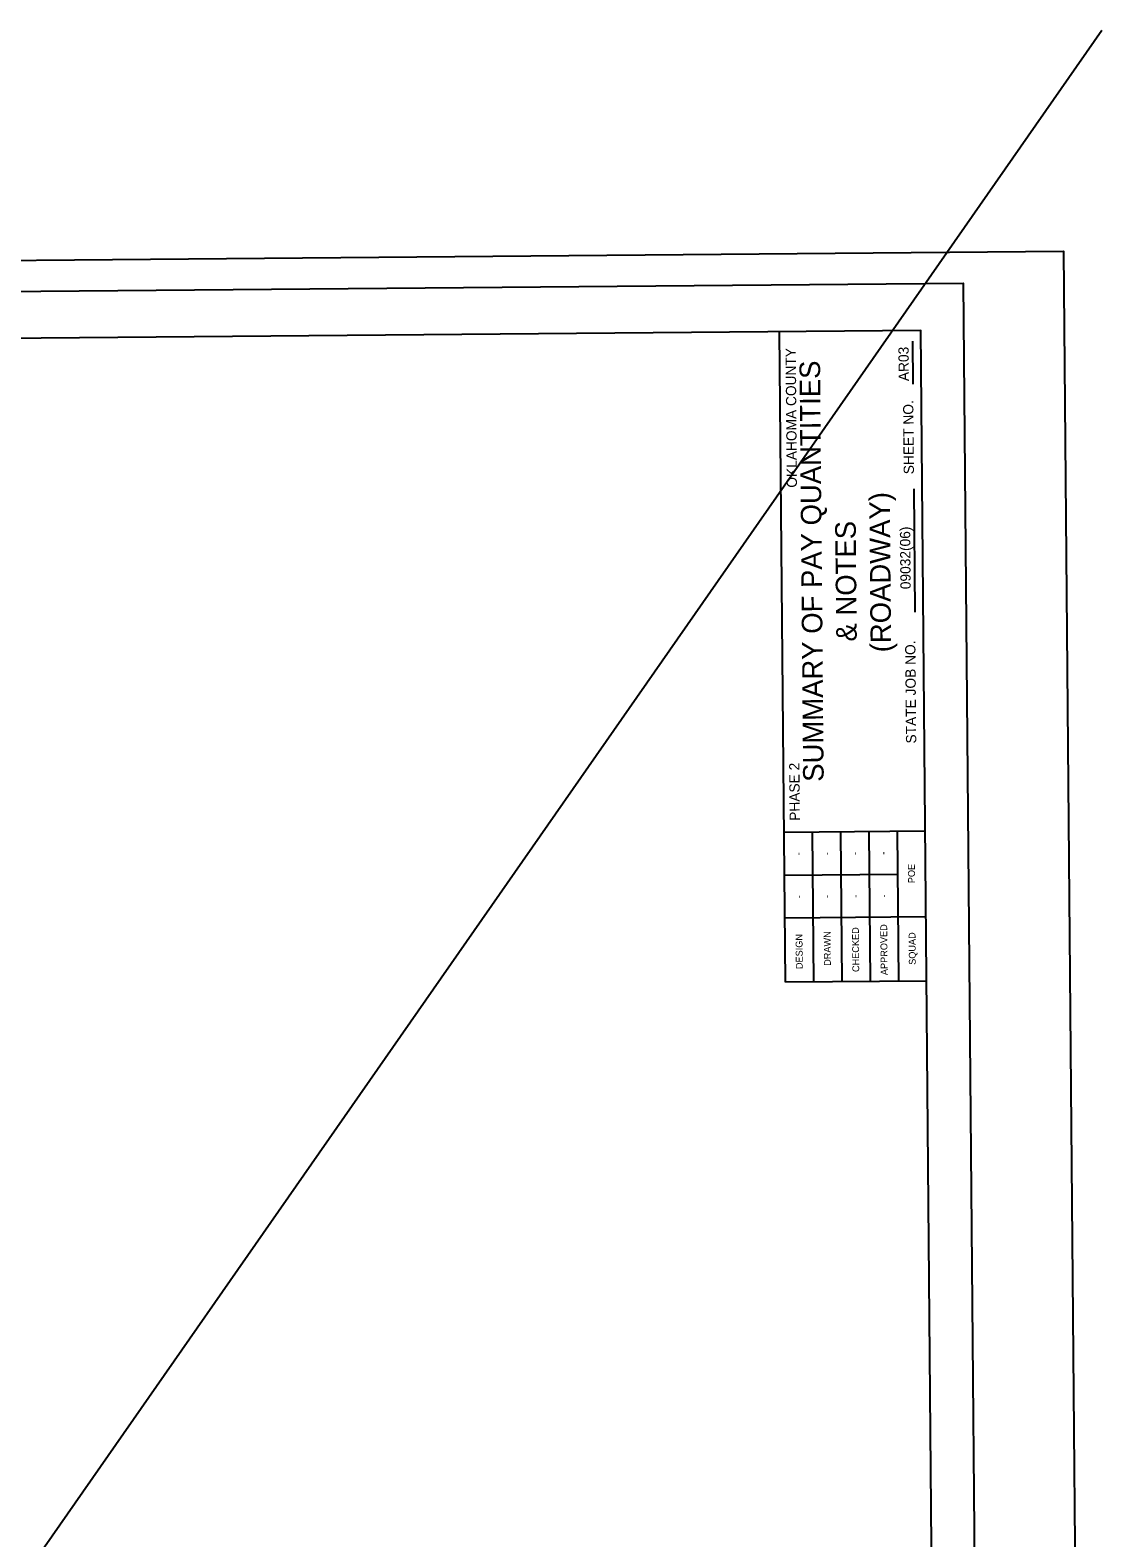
# Model space of a CAD drawing. Extents: x 2151899 to 2151927, y 142567 to 142686.
# Drawn here: x 2151912.01 to 2151924.52, y 142668.37 to 142685.99 of the extents above; entities that cross this region are included whole.
import ezdxf

# ---------------------------------------------------------------- set-up
doc = ezdxf.new("R2010")
doc.units = 0
for name, color, linetype in [('Default', 7, 'Continuous'), ('SHT_Plot_Shape_Full', 7, 'Continuous'), ('SHT_Plot_Shape_Half', 7, 'Continuous'), ('SHT_Sheet_Border', 7, 'Continuous'), ('SHT_Standard_Sheet_Lines', 7, 'Continuous'), ('SHT_Standard_Sheet_Txt', 7, 'Continuous')]:
    doc.layers.add(name, color=color, linetype=linetype)

msp = doc.modelspace()

# ---------------------------------------------------------------- linework, layer by layer
at = {"layer": 'Default'}
msp.add_line((2151899.488, 142650.069), (2151924.522, 142685.989), dxfattribs=at)
at = {"layer": 'SHT_Plot_Shape_Full'}
msp.add_lwpolyline([(2151900.392, 142647.197), (2151900.077, 142683.196), (2151924.076, 142683.406), (2151924.391, 142647.407)], close=True, dxfattribs=at)
at = {"layer": 'SHT_Plot_Shape_Half'}
msp.add_lwpolyline([(2151901.203, 142648.842), (2151900.905, 142682.841), (2151922.904, 142683.033), (2151923.202, 142649.034)], close=True, dxfattribs=at)
at = {"layer": 'SHT_Sheet_Border'}
for p, q in [((2151920.826, 142674.865), (2151920.759, 142682.464)), ((2151922.46, 142676.629), (2151920.809, 142676.614)), ((2151922.476, 142674.879), (2151920.826, 142674.865))]:
    msp.add_line(p, q, dxfattribs=at)
msp.add_lwpolyline([(2151922.685, 142650.98), (2151922.409, 142682.479), (2151901.41, 142682.295), (2151901.686, 142650.796)], close=True, dxfattribs=at)
at = {"layer": 'SHT_Standard_Sheet_Lines'}
for p, q in [((2151922.318, 142681.853), (2151922.314, 142682.356)), ((2151922.342, 142679.189), (2151922.329, 142680.629)), ((2151922.134, 142676.126), (2151920.814, 142676.114)), ((2151922.469, 142675.629), (2151920.818, 142675.614))]:
    msp.add_line(p, q, dxfattribs=at)
for points in [[(2151921.14, 142676.617), (2151921.156, 142674.867)], [(2151921.47, 142676.62), (2151921.486, 142674.87)], [(2151921.8, 142676.623), (2151921.816, 142674.873)], [(2151922.13, 142676.626), (2151922.146, 142674.876)]]:
    msp.add_lwpolyline(points, dxfattribs=at)

# ---------------------------------------------------------------- texts
at = {"layer": 'SHT_Standard_Sheet_Txt'}
for s, height, p in [('OKLAHOMA COUNTY', 0.12, (2151920.962, 142680.644)), ('AR03', 0.12, (2151922.269, 142681.889)), ('SUMMARY OF PAY QUANTITIES', 0.24, (2151921.274, 142677.208)), ('SHEET NO. ', 0.12, (2151922.328, 142680.801)), ('(ROADWAY)', 0.24, (2151922.062, 142678.721)), ('& NOTES', 0.24, (2151921.66, 142678.847)), ('09032(06)', 0.12, (2151922.29, 142679.458)), ('STATE JOB NO.', 0.12, (2151922.355, 142677.655)), ('PHASE 2', 0.12, (2151920.996, 142676.752)), ('-', 0.08, (2151921.017, 142676.347)), ('-', 0.08, (2151921.347, 142676.35)), ('-', 0.08, (2151921.677, 142676.353)), ('-', 0.08, (2151922.007, 142676.355)), ('POE', 0.08, (2151922.34, 142676.023)), ('-', 0.08, (2151921.021, 142675.847)), ('-', 0.08, (2151921.351, 142675.85)), ('-', 0.08, (2151921.682, 142675.853)), ('-', 0.08, (2151922.012, 142675.855)), ('CHECKED', 0.08, (2151921.689, 142674.985)), ('APPROVED', 0.08, (2151922.02, 142674.949)), ('DESIGN', 0.08, (2151921.029, 142675.019)), ('DRAWN', 0.08, (2151921.358, 142675.057)), ('SQUAD', 0.08, (2151922.349, 142675.069))]:
    msp.add_text(s, height=height, rotation=90.5015, dxfattribs=at).set_placement(p)

doc.saveas('drawing.dxf')
